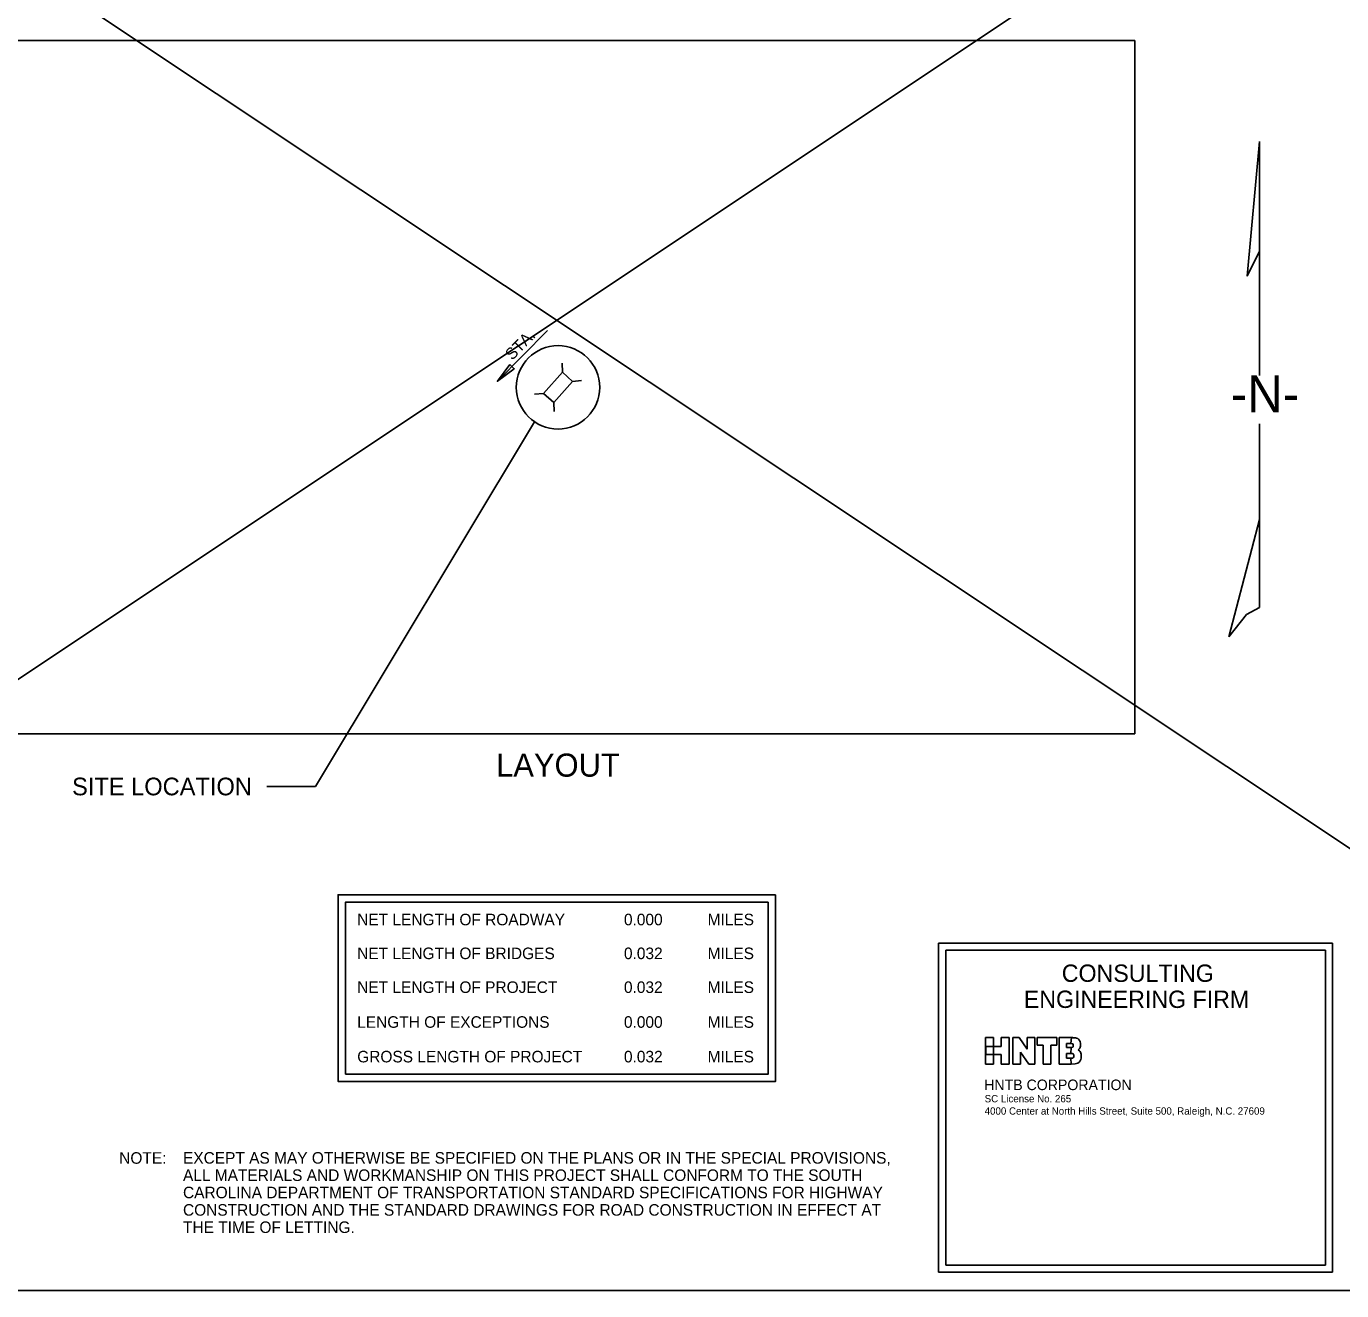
# Model space of a CAD drawing. Extents: x -2.9 to 3.9, y -2.5 to 1.79.
# Drawn here: x -1.999 to -0.814, y 0.042 to 1.182 of the extents above; entities that cross this region are included whole.
import ezdxf

# ---------------------------------------------------------------- set-up
doc = ezdxf.new("R2010")
doc.units = 0
for name, color, linetype in [('BR_AUTO DIMENSION', 7, 'Continuous'), ('BR_BORDER LINES', 7, 'Continuous'), ('BR_DETAILS', 7, 'Continuous'), ('BR_TEXT', 7, 'Continuous'), ('Default', 7, 'Continuous'), ('V7_23', 7, 'Continuous')]:
    doc.layers.add(name, color=color, linetype=linetype)

msp = doc.modelspace()

# ---------------------------------------------------------------- linework, layer by layer
at = {"layer": 'BR_AUTO DIMENSION'}
for p in [(-1.5411, 0.825), (-1.7822, 0.4963)]:
    msp.add_line(p, (-1.7385, 0.4963), dxfattribs=at)
msp.add_circle((-1.5198, 0.8561), 0.0376, dxfattribs=at)
at = {"layer": 'BR_BORDER LINES'}
for points in [[(-2.8333, 1.7917), (-0.2083, 1.7917), (-0.2083, 0.0417), (-2.8333, 0.0417)], [(-2.0417, 0.5438), (-1, 0.5438), (-1, 1.1688), (-2.0417, 1.1688)]]:
    msp.add_lwpolyline(points, close=True, dxfattribs=at)
at = {"layer": 'BR_DETAILS'}
for p, q in [((-1.1768, 0.3551), (-0.8218, 0.3551)), ((-1.1768, 0.0584), (-1.1768, 0.3551)), ((-1.1704, 0.3487), (-0.8282, 0.3487)), ((-1.1704, 0.0648), (-1.1704, 0.3487)), ((-0.8282, 0.3487), (-0.8282, 0.0648)), ((-0.8218, 0.3551), (-0.8218, 0.0584)), ((-0.8282, 0.0648), (-1.1704, 0.0648)), ((-0.8218, 0.0584), (-1.1768, 0.0584))]:
    msp.add_line(p, q, dxfattribs=at)
at = {"layer": 'BR_TEXT'}
for p, q in [((-1.5293, 0.9073), (-1.5744, 0.8616)), ((-1.5159, 0.8697), (-1.5162, 0.8778)), ((-1.5067, 0.8615), (-1.4986, 0.8622)), ((-1.5329, 0.8506), (-1.541, 0.8499)), ((-1.5237, 0.8424), (-1.5234, 0.8343))]:
    msp.add_line(p, q, dxfattribs=at)
for points in [[(-1.5633, 0.8768), (-1.5744, 0.8616), (-1.5593, 0.8729)], [(-1.5159, 0.8697), (-1.5067, 0.8615), (-1.5237, 0.8424), (-1.5329, 0.8506)], [(-1.3237, 0.3987), (-1.718, 0.3987), (-1.718, 0.2303), (-1.3237, 0.2303)], [(-1.3304, 0.392), (-1.7113, 0.392), (-1.7113, 0.237), (-1.3304, 0.237)]]:
    msp.add_lwpolyline(points, close=True, dxfattribs=at)
at = {"layer": 'Default'}
for p, q in [((-2.8333, 1.7917), (-0.2083, 0.0417)), ((-2.8333, 0.0417), (-0.2083, 1.7917)), ((-0.8987, 0.9564), (-0.8876, 1.0778)), ((-0.8876, 1.0778), (-0.8876, 0.979)), ((-0.8876, 0.979), (-0.8987, 0.9564)), ((-0.8876, 0.979), (-0.8876, 0.9105)), ((-0.8876, 0.9105), (-0.8876, 0.8668)), ((-0.8876, 0.8232), (-0.8876, 0.7369)), ((-0.9151, 0.6311), (-0.8876, 0.7369)), ((-0.8876, 0.7369), (-0.8876, 0.7238)), ((-0.8876, 0.7238), (-0.8876, 0.6577))]:
    msp.add_line(p, q, dxfattribs=at)
msp.add_lwpolyline([(-0.8876, 0.6577), (-0.8994, 0.6512), (-0.9151, 0.6311)], dxfattribs=at)
at = {"layer": 'V7_23'}
for p, q in [((-1.1345, 0.2458), (-1.1345, 0.2698)), ((-1.1345, 0.2698), (-1.1274, 0.2698)), ((-1.1274, 0.2617), (-1.1342, 0.2617)), ((-1.1342, 0.2617), (-1.1342, 0.2546)), ((-1.1274, 0.2698), (-1.1274, 0.2617)), ((-1.1274, 0.2546), (-1.1274, 0.2617)), ((-1.1274, 0.2617), (-1.1203, 0.2617)), ((-1.1203, 0.2617), (-1.1203, 0.2698)), ((-1.1203, 0.2698), (-1.1132, 0.2698)), ((-1.1132, 0.2698), (-1.1132, 0.2458)), ((-1.1041, 0.2698), (-1.1099, 0.2698)), ((-1.1099, 0.2698), (-1.1099, 0.2458)), ((-1.097, 0.2593), (-1.1041, 0.2698)), ((-1.09, 0.2698), (-1.097, 0.2698)), ((-1.097, 0.2698), (-1.097, 0.2593)), ((-1.09, 0.2458), (-1.09, 0.2698)), ((-1.088, 0.2698), (-1.088, 0.2629)), ((-1.0703, 0.2698), (-1.088, 0.2698)), ((-1.088, 0.2629), (-1.0827, 0.2629)), ((-1.0827, 0.2629), (-1.0827, 0.2458)), ((-1.0756, 0.2458), (-1.0756, 0.2629)), ((-1.0756, 0.2629), (-1.0703, 0.2629)), ((-1.0703, 0.2629), (-1.0703, 0.2698)), ((-1.0571, 0.2698), (-1.0682, 0.2698)), ((-1.0682, 0.2698), (-1.0682, 0.2458)), ((-1.0616, 0.2609), (-1.0616, 0.2645)), ((-1.0616, 0.2645), (-1.0575, 0.2645)), ((-1.0573, 0.2609), (-1.0616, 0.2609)), ((-1.0576, 0.2556), (-1.0573, 0.2609)), ((-1.0573, 0.2609), (-1.0576, 0.2556)), ((-1.0575, 0.2645), (-1.0571, 0.2698)), ((-1.0571, 0.2698), (-1.0575, 0.2645)), ((-1.1342, 0.2546), (-1.1274, 0.2546)), ((-1.1203, 0.2546), (-1.1274, 0.2546)), ((-1.1274, 0.2546), (-1.1274, 0.2458)), ((-1.1203, 0.2458), (-1.1203, 0.2546)), ((-1.1029, 0.2458), (-1.1029, 0.2566)), ((-1.1029, 0.2566), (-1.0956, 0.2458)), ((-1.0616, 0.2512), (-1.0616, 0.2556)), ((-1.0616, 0.2556), (-1.0576, 0.2556)), ((-1.0575, 0.2512), (-1.0616, 0.2512)), ((-1.0572, 0.2458), (-1.0575, 0.2512)), ((-1.0575, 0.2512), (-1.0572, 0.2458)), ((-1.1274, 0.2458), (-1.1345, 0.2458)), ((-1.1132, 0.2458), (-1.1203, 0.2458)), ((-1.1099, 0.2458), (-1.1029, 0.2458)), ((-1.0956, 0.2458), (-1.09, 0.2458)), ((-1.0827, 0.2458), (-1.0756, 0.2458)), ((-1.0682, 0.2458), (-1.0572, 0.2458))]:
    msp.add_line(p, q, dxfattribs=at)
for points in [[(-1.0575, 0.2645), (-1.0556, 0.2645), (-1.0554, 0.2632), (-1.0554, 0.2627), (-1.0554, 0.2621), (-1.0558, 0.2609), (-1.0573, 0.2609)], [(-1.0509, 0.2588), (-1.0496, 0.2599), (-1.049, 0.2616), (-1.049, 0.2628), (-1.049, 0.2671), (-1.0521, 0.2698), (-1.0571, 0.2698), (-1.0571, 0.2698), (-1.0571, 0.2698), (-1.0571, 0.2698)], [(-1.0576, 0.2556), (-1.0554, 0.2556), (-1.055, 0.2544), (-1.055, 0.2534), (-1.055, 0.252), (-1.0559, 0.2512), (-1.0575, 0.2512)], [(-1.0572, 0.2458), (-1.0517, 0.2458), (-1.0483, 0.2489), (-1.0483, 0.2539), (-1.0483, 0.2558), (-1.0493, 0.2577), (-1.0509, 0.2588)]]:
    msp.add_open_spline(points, degree=3, dxfattribs=at)

# ---------------------------------------------------------------- texts
at = {"layer": 'BR_TEXT'}
for s, height, rotation, p in [('STA.', 0.01042, 45.3959, (-1.5611, 0.88)), ('SITE LOCATION ', 0.015922, 360, (-1.9578, 0.4883)), ('CONSULTING', 0.01563, 0, (-1.0658, 0.3201)), ('ENGINEERING FIRM', 0.015625, 0, (-1.1, 0.2966))]:
    msp.add_text(s, height=height, rotation=rotation, dxfattribs=at).set_placement(p)
for s, height, p in [('HNTB CORPORATION', 0.009516, (-1.1357, 0.2225)), ('SC License No. 265', 0.006558, (-1.1353, 0.2115)), ('4000 Center at North Hills Street, Suite 500, Raleigh, N.C. 27609', 0.006558, (-1.1353, 0.2004))]:
    msp.add_text(s, height=height, dxfattribs=at).set_placement(p)
at = {"layer": 'Default'}
for s, height, p in [('-N-', 0.03333, (-0.9136, 0.8337)), ('LAYOUT', 0.02083, (-1.5756, 0.5051)), ('NET LENGTH OF ROADWAY', 0.010417, (-1.7008, 0.3711)), ('0.000', 0.01042, (-1.4604, 0.3711)), ('MILES', 0.01042, (-1.385, 0.3711)), ('NET LENGTH OF BRIDGES', 0.010417, (-1.7008, 0.3406)), ('0.032', 0.01042, (-1.4604, 0.3406)), ('MILES', 0.01042, (-1.385, 0.3406)), ('NET LENGTH OF PROJECT', 0.010417, (-1.7008, 0.3101)), ('0.032', 0.01042, (-1.4604, 0.3101)), ('MILES', 0.01042, (-1.385, 0.3101)), ('LENGTH OF EXCEPTIONS', 0.010417, (-1.7008, 0.2787)), ('0.000', 0.01042, (-1.4604, 0.2787)), ('MILES', 0.01042, (-1.385, 0.2787)), ('GROSS LENGTH OF PROJECT', 0.010417, (-1.7008, 0.2475)), ('0.032', 0.01042, (-1.4604, 0.2475)), ('MILES', 0.01042, (-1.385, 0.2475)), ('NOTE:', 0.01042, (-1.9153, 0.1561)), ('EXCEPT AS MAY OTHERWISE BE SPECIFIED ON THE PLANS OR IN THE SPECIAL PROVISIONS, ', 0.010417, (-1.8578, 0.1562)), ('ALL MATERIALS AND WORKMANSHIP ON THIS PROJECT SHALL CONFORM TO THE SOUTH ', 0.010417, (-1.8578, 0.1406)), ('CAROLINA DEPARTMENT OF TRANSPORTATION STANDARD SPECIFICATIONS FOR HIGHWAY ', 0.010417, (-1.8578, 0.125)), ('CONSTRUCTION AND THE STANDARD DRAWINGS FOR ROAD CONSTRUCTION IN EFFECT AT ', 0.010417, (-1.8578, 0.1093)), ('THE TIME OF LETTING.', 0.010417, (-1.8578, 0.0937))]:
    msp.add_text(s, height=height, dxfattribs=at).set_placement(p)

doc.saveas('drawing.dxf')
